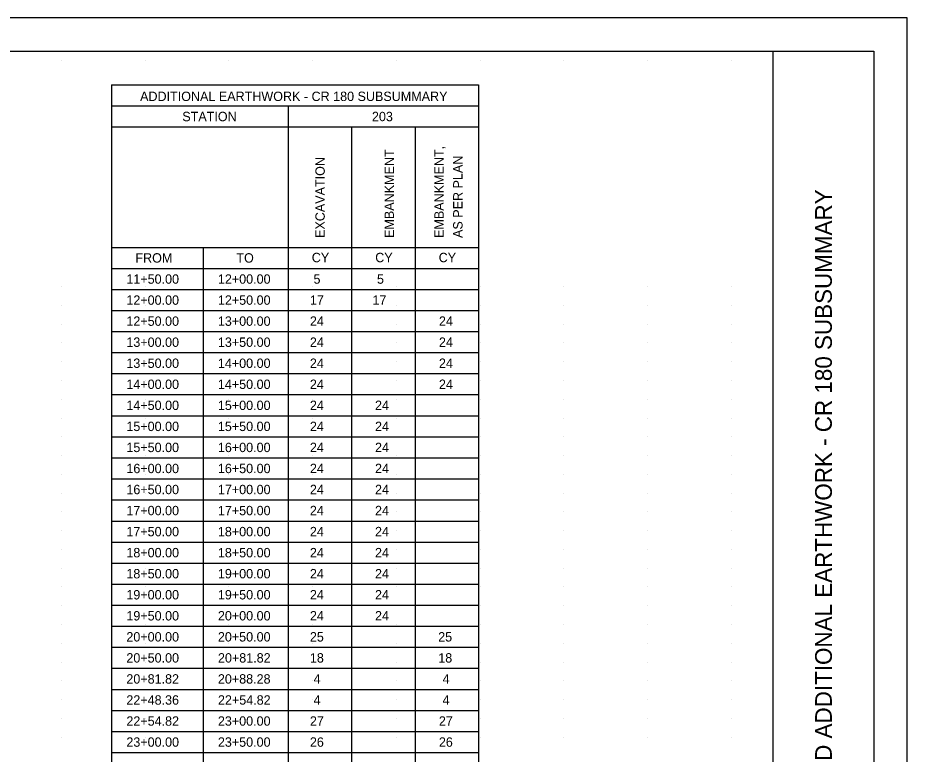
# Model space of a CAD drawing. Extents: x 2073163.9 to 2073197.9, y 634076.5 to 634098.5.
# Drawn here: x 2073184.67 to 2073197.95, y 634087.56 to 634098.55 of the extents above; entities that cross this region are included whole.
import ezdxf

# ---------------------------------------------------------------- set-up
doc = ezdxf.new("R2010")
doc.units = 0
for name, color, linetype in [('SH_Border', 7, 'Continuous'), ('SH_Cut_Line', 7, 'Continuous'), ('SH_Data', 7, 'Continuous'), ('SH_Text', 7, 'Continuous')]:
    doc.layers.add(name, color=color, linetype=linetype)

msp = doc.modelspace()

# ---------------------------------------------------------------- linework, layer by layer
at = {"layer": 'SH_Border'}
for p, q in [((2073195.946, 634077.05), (2073195.946, 634098.05)), ((2073186.071, 634097.55), (2073191.547, 634097.55)), ((2073186.071, 634097.55), (2073186.071, 634081.026)), ((2073191.547, 634097.55), (2073191.547, 634081.026))]:
    msp.add_line(p, q, dxfattribs=at)
msp.add_lwpolyline([(2073165.446, 634098.05), (2073197.446, 634098.05), (2073197.446, 634077.05), (2073165.446, 634077.05)], close=True, dxfattribs=at)
at = {"layer": 'SH_Cut_Line'}
msp.add_lwpolyline([(2073163.946, 634076.55), (2073197.946, 634076.55), (2073197.946, 634098.55), (2073163.946, 634098.55)], close=True, dxfattribs=at)
at = {"layer": 'SH_Data'}
for p, q in [((2073185.321, 634097.91), (2073185.321, 634097.91)), ((2073185.321, 634097.91), (2073185.321, 634097.91)), ((2073185.321, 634097.91), (2073185.321, 634097.91)), ((2073185.321, 634097.91), (2073185.321, 634097.91)), ((2073185.321, 634097.91), (2073185.321, 634097.91)), ((2073186.571, 634097.91), (2073186.571, 634097.91)), ((2073187.821, 634097.91), (2073187.821, 634097.91)), ((2073189.071, 634097.91), (2073189.071, 634097.91)), ((2073190.321, 634097.91), (2073190.321, 634097.91)), ((2073191.571, 634097.91), (2073191.571, 634097.91)), ((2073192.821, 634097.91), (2073192.821, 634097.91)), ((2073194.071, 634097.91), (2073194.071, 634097.91)), ((2073195.321, 634097.91), (2073195.321, 634097.91)), ((2073185.321, 634094.538), (2073185.321, 634094.538)), ((2073185.321, 634094.538), (2073185.321, 634094.538)), ((2073185.321, 634094.538), (2073185.321, 634094.538)), ((2073185.321, 634094.538), (2073185.321, 634094.538)), ((2073185.321, 634094.538), (2073185.321, 634094.538)), ((2073186.571, 634094.538), (2073186.571, 634094.538)), ((2073187.821, 634094.538), (2073187.821, 634094.538)), ((2073189.071, 634094.538), (2073189.071, 634094.538)), ((2073190.321, 634094.538), (2073190.321, 634094.538)), ((2073191.571, 634094.538), (2073191.571, 634094.538)), ((2073192.821, 634094.538), (2073192.821, 634094.538)), ((2073194.071, 634094.538), (2073194.071, 634094.538)), ((2073195.321, 634094.538), (2073195.321, 634094.538)), ((2073185.321, 634094.258), (2073185.321, 634094.258)), ((2073186.571, 634094.258), (2073186.571, 634094.258)), ((2073187.821, 634094.258), (2073187.821, 634094.258)), ((2073189.071, 634094.258), (2073189.071, 634094.258)), ((2073190.321, 634094.258), (2073190.321, 634094.258)), ((2073191.571, 634094.258), (2073191.571, 634094.258)), ((2073192.821, 634094.258), (2073192.821, 634094.258)), ((2073194.071, 634094.258), (2073194.071, 634094.258)), ((2073195.321, 634094.258), (2073195.321, 634094.258)), ((2073185.321, 634093.978), (2073185.321, 634093.978)), ((2073186.571, 634093.978), (2073186.571, 634093.978)), ((2073187.821, 634093.978), (2073187.821, 634093.978)), ((2073189.071, 634093.978), (2073189.071, 634093.978)), ((2073190.321, 634093.978), (2073190.321, 634093.978)), ((2073191.571, 634093.978), (2073191.571, 634093.978)), ((2073192.821, 634093.978), (2073192.821, 634093.978)), ((2073194.071, 634093.978), (2073194.071, 634093.978)), ((2073195.321, 634093.978), (2073195.321, 634093.978)), ((2073185.321, 634093.698), (2073185.321, 634093.698)), ((2073186.571, 634093.698), (2073186.571, 634093.698)), ((2073187.821, 634093.698), (2073187.821, 634093.698)), ((2073189.071, 634093.698), (2073189.071, 634093.698)), ((2073190.321, 634093.698), (2073190.321, 634093.698)), ((2073191.571, 634093.698), (2073191.571, 634093.698)), ((2073192.821, 634093.698), (2073192.821, 634093.698)), ((2073194.071, 634093.698), (2073194.071, 634093.698)), ((2073195.321, 634093.698), (2073195.321, 634093.698)), ((2073185.321, 634093.418), (2073185.321, 634093.418)), ((2073186.571, 634093.418), (2073186.571, 634093.418)), ((2073187.821, 634093.418), (2073187.821, 634093.418)), ((2073189.071, 634093.418), (2073189.071, 634093.418)), ((2073190.321, 634093.418), (2073190.321, 634093.418)), ((2073191.571, 634093.418), (2073191.571, 634093.418)), ((2073192.821, 634093.418), (2073192.821, 634093.418)), ((2073194.071, 634093.418), (2073194.071, 634093.418)), ((2073195.321, 634093.418), (2073195.321, 634093.418)), ((2073185.321, 634093.138), (2073185.321, 634093.138)), ((2073186.571, 634093.138), (2073186.571, 634093.138)), ((2073187.821, 634093.138), (2073187.821, 634093.138)), ((2073189.071, 634093.138), (2073189.071, 634093.138)), ((2073190.321, 634093.138), (2073190.321, 634093.138)), ((2073191.571, 634093.138), (2073191.571, 634093.138)), ((2073192.821, 634093.138), (2073192.821, 634093.138)), ((2073194.071, 634093.138), (2073194.071, 634093.138)), ((2073195.321, 634093.138), (2073195.321, 634093.138)), ((2073185.321, 634092.858), (2073185.321, 634092.858)), ((2073186.571, 634092.858), (2073186.571, 634092.858)), ((2073187.821, 634092.858), (2073187.821, 634092.858)), ((2073189.071, 634092.858), (2073189.071, 634092.858)), ((2073190.321, 634092.858), (2073190.321, 634092.858)), ((2073191.571, 634092.858), (2073191.571, 634092.858)), ((2073192.821, 634092.858), (2073192.821, 634092.858)), ((2073194.071, 634092.858), (2073194.071, 634092.858)), ((2073195.321, 634092.858), (2073195.321, 634092.858)), ((2073185.321, 634092.578), (2073185.321, 634092.578)), ((2073186.571, 634092.578), (2073186.571, 634092.578)), ((2073187.821, 634092.578), (2073187.821, 634092.578)), ((2073189.071, 634092.578), (2073189.071, 634092.578)), ((2073190.321, 634092.578), (2073190.321, 634092.578)), ((2073191.571, 634092.578), (2073191.571, 634092.578)), ((2073192.821, 634092.578), (2073192.821, 634092.578)), ((2073194.071, 634092.578), (2073194.071, 634092.578)), ((2073195.321, 634092.578), (2073195.321, 634092.578)), ((2073185.321, 634092.298), (2073185.321, 634092.298)), ((2073186.571, 634092.298), (2073186.571, 634092.298)), ((2073187.821, 634092.298), (2073187.821, 634092.298)), ((2073189.071, 634092.298), (2073189.071, 634092.298)), ((2073190.321, 634092.298), (2073190.321, 634092.298)), ((2073191.571, 634092.298), (2073191.571, 634092.298)), ((2073192.821, 634092.298), (2073192.821, 634092.298)), ((2073194.071, 634092.298), (2073194.071, 634092.298)), ((2073195.321, 634092.298), (2073195.321, 634092.298)), ((2073185.321, 634092.018), (2073185.321, 634092.018)), ((2073186.571, 634092.018), (2073186.571, 634092.018)), ((2073187.821, 634092.018), (2073187.821, 634092.018)), ((2073189.071, 634092.018), (2073189.071, 634092.018)), ((2073190.321, 634092.018), (2073190.321, 634092.018)), ((2073191.571, 634092.018), (2073191.571, 634092.018)), ((2073192.821, 634092.018), (2073192.821, 634092.018)), ((2073194.071, 634092.018), (2073194.071, 634092.018)), ((2073195.321, 634092.018), (2073195.321, 634092.018)), ((2073185.321, 634091.738), (2073185.321, 634091.738)), ((2073186.571, 634091.738), (2073186.571, 634091.738)), ((2073187.821, 634091.738), (2073187.821, 634091.738)), ((2073189.071, 634091.738), (2073189.071, 634091.738)), ((2073190.321, 634091.738), (2073190.321, 634091.738)), ((2073191.571, 634091.738), (2073191.571, 634091.738)), ((2073192.821, 634091.738), (2073192.821, 634091.738)), ((2073194.071, 634091.738), (2073194.071, 634091.738)), ((2073195.321, 634091.738), (2073195.321, 634091.738)), ((2073185.321, 634091.458), (2073185.321, 634091.458)), ((2073186.571, 634091.458), (2073186.571, 634091.458)), ((2073187.821, 634091.458), (2073187.821, 634091.458)), ((2073189.071, 634091.458), (2073189.071, 634091.458)), ((2073190.321, 634091.458), (2073190.321, 634091.458)), ((2073191.571, 634091.458), (2073191.571, 634091.458)), ((2073192.821, 634091.458), (2073192.821, 634091.458)), ((2073194.071, 634091.458), (2073194.071, 634091.458)), ((2073195.321, 634091.458), (2073195.321, 634091.458)), ((2073185.321, 634091.178), (2073185.321, 634091.178)), ((2073186.571, 634091.178), (2073186.571, 634091.178)), ((2073187.821, 634091.178), (2073187.821, 634091.178)), ((2073189.071, 634091.178), (2073189.071, 634091.178)), ((2073190.321, 634091.178), (2073190.321, 634091.178)), ((2073191.571, 634091.178), (2073191.571, 634091.178)), ((2073192.821, 634091.178), (2073192.821, 634091.178)), ((2073194.071, 634091.178), (2073194.071, 634091.178)), ((2073195.321, 634091.178), (2073195.321, 634091.178)), ((2073185.321, 634090.898), (2073185.321, 634090.898)), ((2073186.571, 634090.898), (2073186.571, 634090.898)), ((2073187.821, 634090.898), (2073187.821, 634090.898)), ((2073189.071, 634090.898), (2073189.071, 634090.898)), ((2073190.321, 634090.898), (2073190.321, 634090.898)), ((2073191.571, 634090.898), (2073191.571, 634090.898)), ((2073192.821, 634090.898), (2073192.821, 634090.898)), ((2073194.071, 634090.898), (2073194.071, 634090.898)), ((2073195.321, 634090.898), (2073195.321, 634090.898)), ((2073185.321, 634090.618), (2073185.321, 634090.618)), ((2073186.571, 634090.618), (2073186.571, 634090.618)), ((2073187.821, 634090.618), (2073187.821, 634090.618)), ((2073189.071, 634090.618), (2073189.071, 634090.618)), ((2073190.321, 634090.618), (2073190.321, 634090.618)), ((2073191.571, 634090.618), (2073191.571, 634090.618)), ((2073192.821, 634090.618), (2073192.821, 634090.618)), ((2073194.071, 634090.618), (2073194.071, 634090.618)), ((2073195.321, 634090.618), (2073195.321, 634090.618)), ((2073185.321, 634090.338), (2073185.321, 634090.338)), ((2073186.571, 634090.338), (2073186.571, 634090.338)), ((2073187.821, 634090.338), (2073187.821, 634090.338)), ((2073189.071, 634090.338), (2073189.071, 634090.338)), ((2073190.321, 634090.338), (2073190.321, 634090.338)), ((2073191.571, 634090.338), (2073191.571, 634090.338)), ((2073192.821, 634090.338), (2073192.821, 634090.338)), ((2073194.071, 634090.338), (2073194.071, 634090.338)), ((2073195.321, 634090.338), (2073195.321, 634090.338)), ((2073185.321, 634090.058), (2073185.321, 634090.058)), ((2073186.571, 634090.058), (2073186.571, 634090.058)), ((2073187.821, 634090.058), (2073187.821, 634090.058)), ((2073189.071, 634090.058), (2073189.071, 634090.058)), ((2073190.321, 634090.058), (2073190.321, 634090.058)), ((2073191.571, 634090.058), (2073191.571, 634090.058)), ((2073192.821, 634090.058), (2073192.821, 634090.058)), ((2073194.071, 634090.058), (2073194.071, 634090.058)), ((2073195.321, 634090.058), (2073195.321, 634090.058)), ((2073185.321, 634089.778), (2073185.321, 634089.778)), ((2073186.571, 634089.778), (2073186.571, 634089.778)), ((2073187.821, 634089.778), (2073187.821, 634089.778)), ((2073189.071, 634089.778), (2073189.071, 634089.778)), ((2073190.321, 634089.778), (2073190.321, 634089.778)), ((2073191.571, 634089.778), (2073191.571, 634089.778)), ((2073192.821, 634089.778), (2073192.821, 634089.778)), ((2073194.071, 634089.778), (2073194.071, 634089.778)), ((2073195.321, 634089.778), (2073195.321, 634089.778)), ((2073185.321, 634089.498), (2073185.321, 634089.498)), ((2073186.571, 634089.498), (2073186.571, 634089.498)), ((2073187.821, 634089.498), (2073187.821, 634089.498)), ((2073189.071, 634089.498), (2073189.071, 634089.498)), ((2073190.321, 634089.498), (2073190.321, 634089.498)), ((2073191.571, 634089.498), (2073191.571, 634089.498)), ((2073192.821, 634089.498), (2073192.821, 634089.498)), ((2073194.071, 634089.498), (2073194.071, 634089.498)), ((2073195.321, 634089.498), (2073195.321, 634089.498)), ((2073185.321, 634089.218), (2073185.321, 634089.218)), ((2073186.571, 634089.218), (2073186.571, 634089.218)), ((2073187.821, 634089.218), (2073187.821, 634089.218)), ((2073189.071, 634089.218), (2073189.071, 634089.218)), ((2073190.321, 634089.218), (2073190.321, 634089.218)), ((2073191.571, 634089.218), (2073191.571, 634089.218)), ((2073192.821, 634089.218), (2073192.821, 634089.218)), ((2073194.071, 634089.218), (2073194.071, 634089.218)), ((2073195.321, 634089.218), (2073195.321, 634089.218)), ((2073185.321, 634088.938), (2073185.321, 634088.938)), ((2073186.571, 634088.938), (2073186.571, 634088.938)), ((2073187.821, 634088.938), (2073187.821, 634088.938)), ((2073189.071, 634088.938), (2073189.071, 634088.938)), ((2073190.321, 634088.938), (2073190.321, 634088.938)), ((2073191.571, 634088.938), (2073191.571, 634088.938)), ((2073192.821, 634088.938), (2073192.821, 634088.938)), ((2073194.071, 634088.938), (2073194.071, 634088.938)), ((2073195.321, 634088.938), (2073195.321, 634088.938)), ((2073185.321, 634088.658), (2073185.321, 634088.658)), ((2073186.571, 634088.658), (2073186.571, 634088.658)), ((2073187.821, 634088.658), (2073187.821, 634088.658)), ((2073189.071, 634088.658), (2073189.071, 634088.658)), ((2073190.321, 634088.658), (2073190.321, 634088.658)), ((2073191.571, 634088.658), (2073191.571, 634088.658)), ((2073192.821, 634088.658), (2073192.821, 634088.658)), ((2073194.071, 634088.658), (2073194.071, 634088.658)), ((2073195.321, 634088.658), (2073195.321, 634088.658)), ((2073185.321, 634088.378), (2073185.321, 634088.378)), ((2073186.571, 634088.378), (2073186.571, 634088.378)), ((2073187.821, 634088.378), (2073187.821, 634088.378)), ((2073189.071, 634088.378), (2073189.071, 634088.378)), ((2073190.321, 634088.378), (2073190.321, 634088.378)), ((2073191.571, 634088.378), (2073191.571, 634088.378)), ((2073192.821, 634088.378), (2073192.821, 634088.378)), ((2073194.071, 634088.378), (2073194.071, 634088.378)), ((2073195.321, 634088.378), (2073195.321, 634088.378)), ((2073185.321, 634088.098), (2073185.321, 634088.098)), ((2073186.571, 634088.098), (2073186.571, 634088.098)), ((2073187.821, 634088.098), (2073187.821, 634088.098)), ((2073189.071, 634088.098), (2073189.071, 634088.098)), ((2073190.321, 634088.098), (2073190.321, 634088.098)), ((2073191.571, 634088.098), (2073191.571, 634088.098)), ((2073192.821, 634088.098), (2073192.821, 634088.098)), ((2073194.071, 634088.098), (2073194.071, 634088.098)), ((2073195.321, 634088.098), (2073195.321, 634088.098)), ((2073185.321, 634087.818), (2073185.321, 634087.818)), ((2073186.571, 634087.818), (2073186.571, 634087.818)), ((2073187.821, 634087.818), (2073187.821, 634087.818)), ((2073189.071, 634087.818), (2073189.071, 634087.818)), ((2073190.321, 634087.818), (2073190.321, 634087.818)), ((2073191.571, 634087.818), (2073191.571, 634087.818)), ((2073192.821, 634087.818), (2073192.821, 634087.818)), ((2073194.071, 634087.818), (2073194.071, 634087.818)), ((2073195.321, 634087.818), (2073195.321, 634087.818))]:
    msp.add_line(p, q, dxfattribs=at)
at = {"layer": 'SH_Text'}
for p, q in [((2073186.071, 634097.236), (2073191.547, 634097.236)), ((2073188.706, 634097.236), (2073188.706, 634081.026)), ((2073186.071, 634096.922), (2073191.547, 634096.922)), ((2073189.653, 634096.922), (2073189.653, 634081.026)), ((2073190.6, 634096.922), (2073190.6, 634081.026)), ((2073186.071, 634095.125), (2073191.547, 634095.125)), ((2073187.436, 634095.125), (2073187.436, 634081.621)), ((2073186.071, 634094.811), (2073191.547, 634094.811)), ((2073186.071, 634094.497), (2073191.547, 634094.497)), ((2073186.071, 634094.183), (2073191.547, 634094.183)), ((2073186.071, 634093.869), (2073191.547, 634093.869)), ((2073186.071, 634093.555), (2073191.547, 634093.555)), ((2073186.071, 634093.241), (2073191.547, 634093.241)), ((2073186.071, 634092.927), (2073191.547, 634092.927)), ((2073186.071, 634092.613), (2073191.547, 634092.613)), ((2073186.071, 634092.299), (2073191.547, 634092.299)), ((2073186.071, 634091.985), (2073191.547, 634091.985)), ((2073186.071, 634091.67), (2073191.547, 634091.67)), ((2073186.071, 634091.356), (2073191.547, 634091.356)), ((2073186.071, 634091.042), (2073191.547, 634091.042)), ((2073186.071, 634090.728), (2073191.547, 634090.728)), ((2073186.071, 634090.414), (2073191.547, 634090.414)), ((2073186.071, 634090.1), (2073191.547, 634090.1)), ((2073186.071, 634089.786), (2073191.547, 634089.786)), ((2073186.071, 634089.472), (2073191.547, 634089.472)), ((2073186.071, 634089.158), (2073191.547, 634089.158)), ((2073186.071, 634088.844), (2073191.547, 634088.844)), ((2073186.071, 634088.53), (2073191.547, 634088.53)), ((2073186.071, 634088.216), (2073191.547, 634088.216)), ((2073186.071, 634087.902), (2073191.547, 634087.902)), ((2073186.071, 634087.588), (2073191.547, 634087.588))]:
    msp.add_line(p, q, dxfattribs=at)

# ---------------------------------------------------------------- texts
at = {"layer": 'SH_Data'}
msp.add_text('DRIVEWAY SUBSUMMARY AND ADDITIONAL EARTHWORK - CR 180 SUBSUMMARY', height=0.25, rotation=90, dxfattribs=at).set_placement((2073196.821, 634082.634))
at = {"layer": 'SH_Text'}
for s, p in [('ADDITIONAL EARTHWORK - CR 180 SUBSUMMARY', (2073186.497, 634097.308)), ('STATION', (2073187.127, 634097.007)), ('203', (2073189.957, 634097.007)), ('FROM', (2073186.427, 634094.897)), ('TO', (2073187.934, 634094.897)), ('CY', (2073189.059, 634094.903)), ('CY', (2073190.006, 634094.903)), ('CY', (2073190.953, 634094.903)), ('11+50.00', (2073186.292, 634094.582)), ('12+00.00', (2073187.658, 634094.582)), ('5', (2073189.085, 634094.582)), ('5', (2073190.032, 634094.582)), ('12+00.00', (2073186.292, 634094.268)), ('12+50.00', (2073187.658, 634094.268)), ('17', (2073189.031, 634094.268)), ('17', (2073189.965, 634094.268)), ('12+50.00', (2073186.292, 634093.954)), ('13+00.00', (2073187.658, 634093.954)), ('24', (2073189.031, 634093.954)), ('24', (2073190.957, 634093.954)), ('13+00.00', (2073186.292, 634093.64)), ('13+50.00', (2073187.658, 634093.64)), ('24', (2073189.031, 634093.64)), ('24', (2073190.957, 634093.64)), ('13+50.00', (2073186.292, 634093.326)), ('14+00.00', (2073187.658, 634093.326)), ('24', (2073189.031, 634093.326)), ('24', (2073190.957, 634093.326)), ('14+00.00', (2073186.292, 634093.012)), ('14+50.00', (2073187.658, 634093.012)), ('24', (2073189.031, 634093.012)), ('24', (2073190.957, 634093.012)), ('14+50.00', (2073186.292, 634092.698)), ('15+00.00', (2073187.658, 634092.698)), ('24', (2073189.031, 634092.698)), ('24', (2073190.003, 634092.698)), ('15+00.00', (2073186.292, 634092.384)), ('15+50.00', (2073187.658, 634092.384)), ('24', (2073189.031, 634092.384)), ('24', (2073190.003, 634092.384)), ('15+50.00', (2073186.292, 634092.07)), ('16+00.00', (2073187.658, 634092.07)), ('24', (2073189.031, 634092.07)), ('24', (2073190.003, 634092.07)), ('16+00.00', (2073186.292, 634091.756)), ('16+50.00', (2073187.658, 634091.756)), ('24', (2073189.031, 634091.756)), ('24', (2073190.003, 634091.756)), ('16+50.00', (2073186.292, 634091.442)), ('17+00.00', (2073187.658, 634091.442)), ('24', (2073189.031, 634091.442)), ('24', (2073190.003, 634091.442)), ('17+00.00', (2073186.292, 634091.128)), ('17+50.00', (2073187.658, 634091.128)), ('24', (2073189.031, 634091.128)), ('24', (2073190.003, 634091.128)), ('17+50.00', (2073186.292, 634090.814)), ('18+00.00', (2073187.658, 634090.814)), ('24', (2073189.031, 634090.814)), ('24', (2073190.003, 634090.814)), ('18+00.00', (2073186.292, 634090.5)), ('18+50.00', (2073187.658, 634090.5)), ('24', (2073189.031, 634090.5)), ('24', (2073190.003, 634090.5)), ('18+50.00', (2073186.292, 634090.186)), ('19+00.00', (2073187.658, 634090.186)), ('24', (2073189.031, 634090.186)), ('24', (2073190.003, 634090.186)), ('19+00.00', (2073186.292, 634089.872)), ('19+50.00', (2073187.658, 634089.872)), ('24', (2073189.031, 634089.872)), ('24', (2073190.003, 634089.872)), ('19+50.00', (2073186.292, 634089.558)), ('20+00.00', (2073187.658, 634089.558)), ('24', (2073189.031, 634089.558)), ('24', (2073190.003, 634089.558)), ('20+00.00', (2073186.292, 634089.244)), ('20+50.00', (2073187.658, 634089.244)), ('25', (2073189.031, 634089.244)), ('25', (2073190.946, 634089.244)), ('20+50.00', (2073186.292, 634088.93)), ('20+81.82', (2073187.659, 634088.93)), ('18', (2073189.031, 634088.93)), ('18', (2073190.947, 634088.93)), ('20+81.82', (2073186.292, 634088.616)), ('20+88.28', (2073187.658, 634088.616)), ('4', (2073189.086, 634088.616)), ('4', (2073191.011, 634088.616)), ('22+48.36', (2073186.292, 634088.302)), ('22+54.82', (2073187.659, 634088.302)), ('4', (2073189.086, 634088.302)), ('4', (2073191.011, 634088.302)), ('22+54.82', (2073186.292, 634087.988)), ('23+00.00', (2073187.658, 634087.988)), ('27', (2073189.031, 634087.988)), ('27', (2073190.956, 634087.988)), ('23+00.00', (2073186.292, 634087.674)), ('23+50.00', (2073187.658, 634087.674)), ('26', (2073189.031, 634087.674)), ('26', (2073190.956, 634087.674))]:
    msp.add_text(s, height=0.14, dxfattribs=at).set_placement(p)
for s, p in [('EMBANKMENT', (2073190.285, 634095.265)), ('EMBANKMENT,', (2073191.029, 634095.265)), ('EXCAVATION', (2073189.253, 634095.265)), ('AS PER PLAN', (2073191.309, 634095.265))]:
    msp.add_text(s, height=0.14, rotation=90, dxfattribs=at).set_placement(p)

doc.saveas('drawing.dxf')
